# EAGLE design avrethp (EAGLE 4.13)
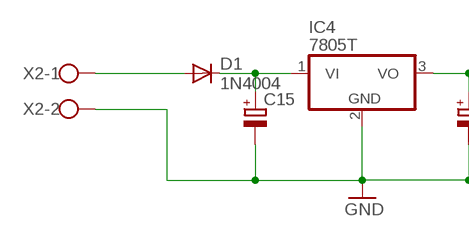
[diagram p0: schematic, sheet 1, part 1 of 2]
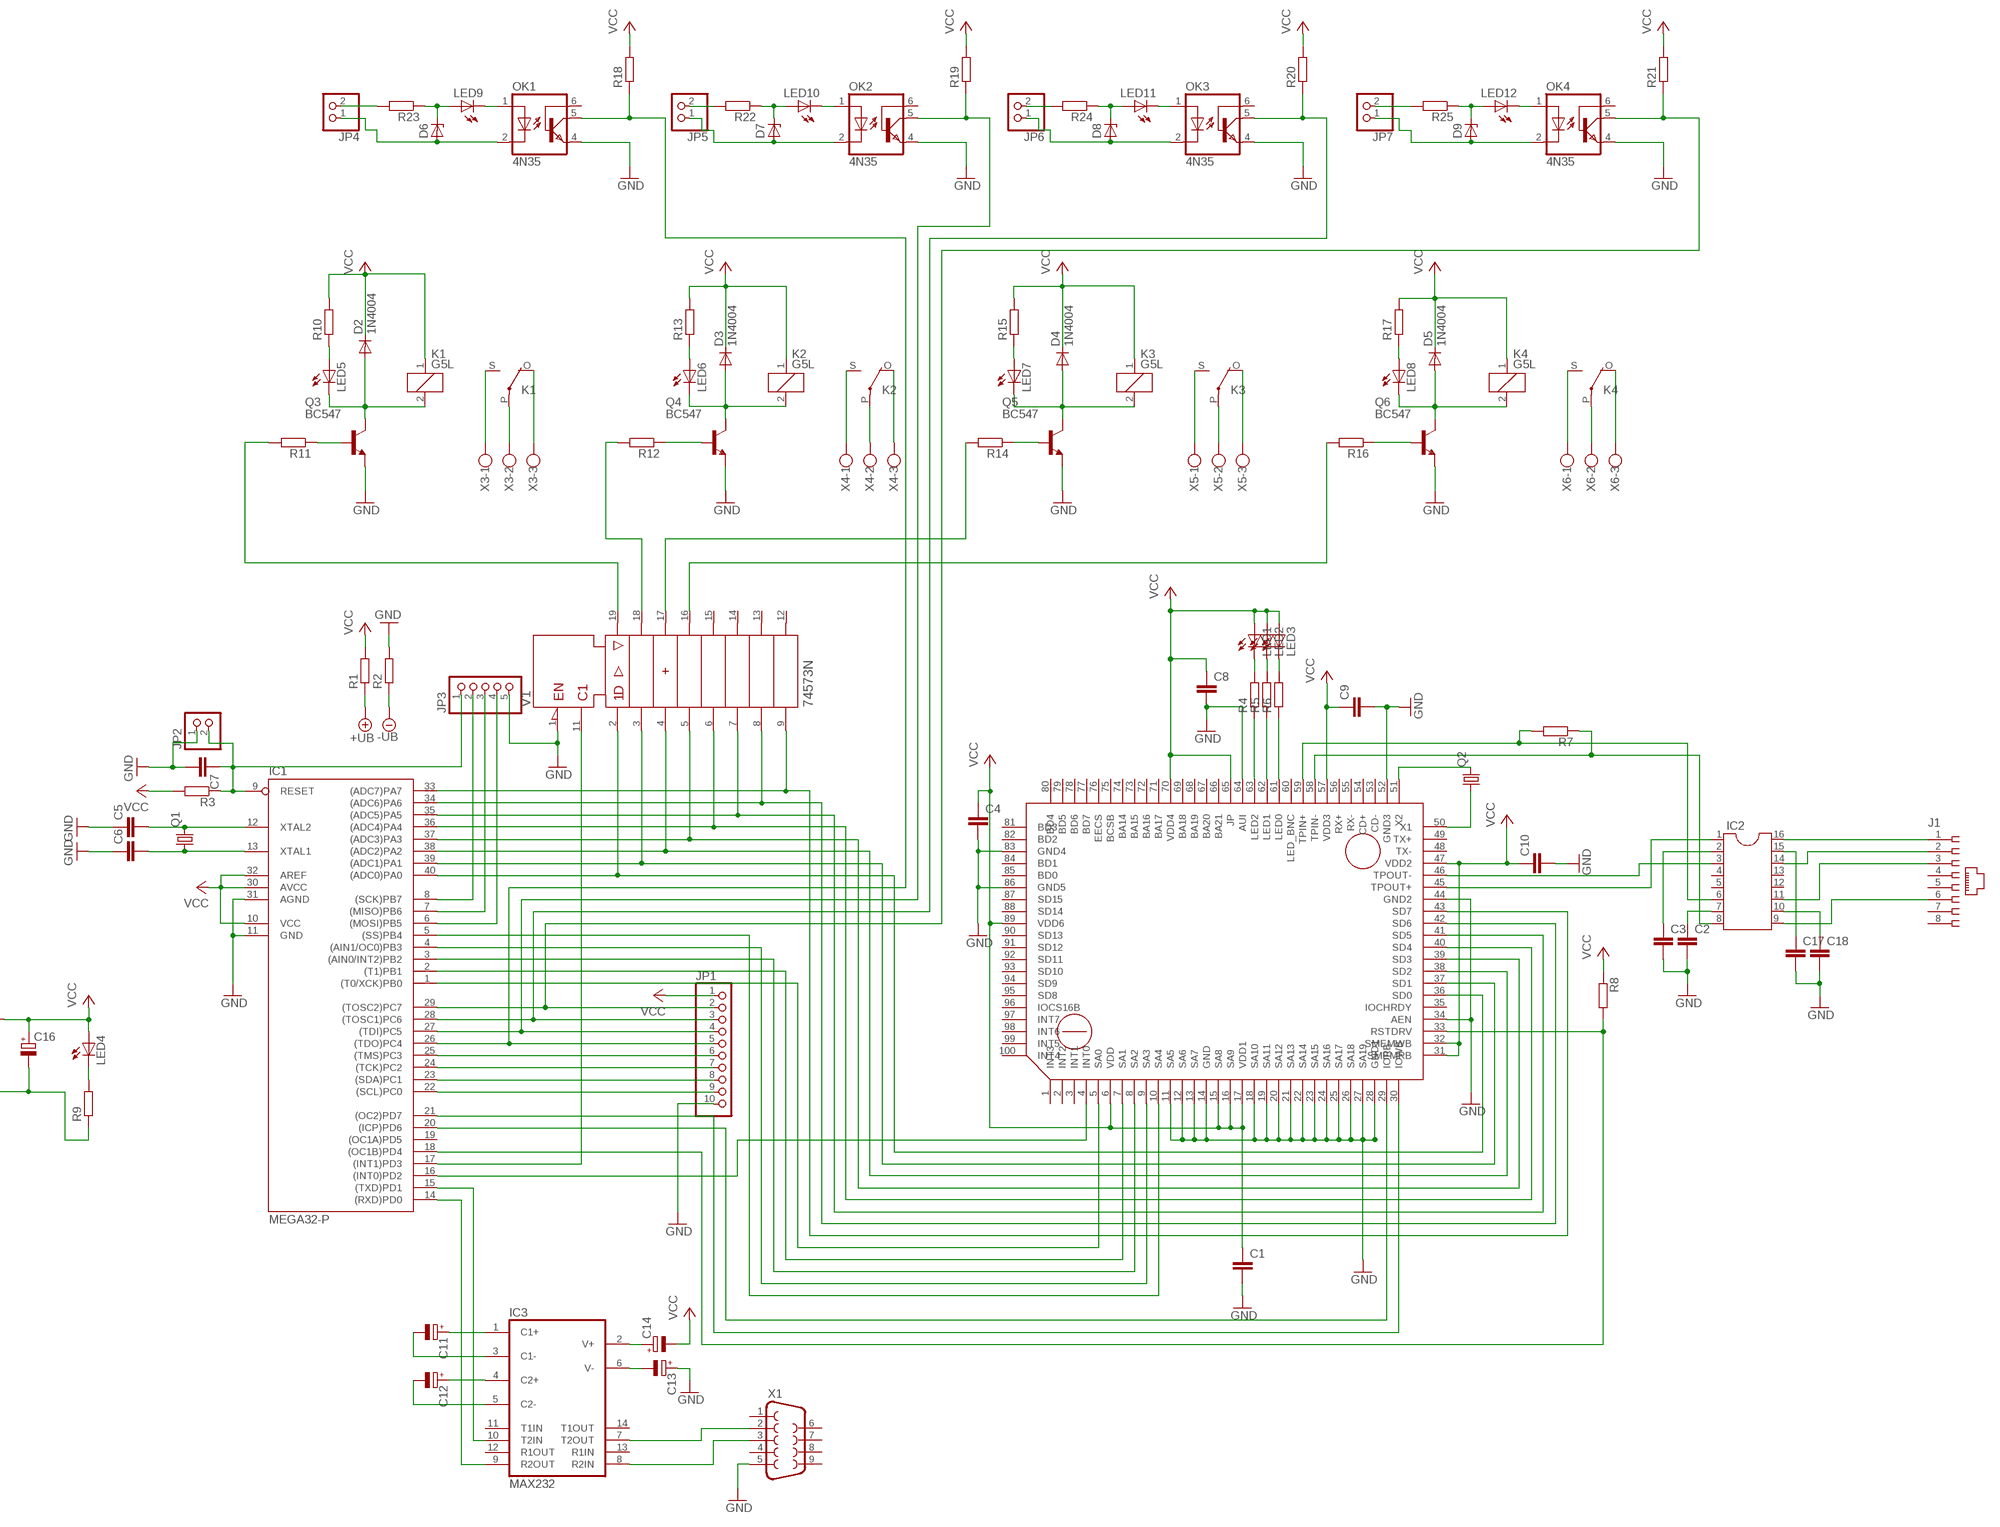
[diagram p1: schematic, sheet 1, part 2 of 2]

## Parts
C1  C-EU050-024X044  [C050-024X044]
C2  C-EU050-024X044  [C050-024X044]
C3  C-EU050-024X044  [C050-024X044]
C4  C-EU050-024X044  [C050-024X044]
C5  C-EU050-024X044  [C050-024X044]
C6  C-EU050-024X044  [C050-024X044]
C7  C-EU050-024X044  [C050-024X044]
C8  C-EU050-024X044  [C050-024X044]
C9  C-EU050-024X044  [C050-024X044]
C10  C-EU050-024X044  [C050-024X044]
C11  CPOL-EUE5-5  [E5-5]
C12  CPOL-EUE5-5  [E5-5]
C13  CPOL-EUE5-5  [E5-5]
C14  CPOL-EUE5-5  [E5-5]
C15  CPOL-EUE5-8.5  [E5-8,5]
C16  CPOL-EUE5-5  [E5-5]
C17  C-EU050-024X044  [C050-024X044]
C18  C-EU050-024X044  [C050-024X044]
D1  1N4004  [DO41-10]
D2  1N4004  [DO41-10]
D3  1N4004  [DO41-10]
D4  1N4004  [DO41-10]
D5  1N4004  [DO41-10]
D6  ZENER-DIODEZD-7.5  [ZDIO-7.5]
D7  ZENER-DIODEZD-7.5  [ZDIO-7.5]
D8  ZENER-DIODEZD-7.5  [ZDIO-7.5]
D9  ZENER-DIODEZD-7.5  [ZDIO-7.5]
IC1  MEGA32-P  [DIL40]
IC2  DIL16  [DIL16]
IC3  MAX232  [DIL16]
IC4  7805T  [TO220H]
J1  520251-4  [520251-4]
JP1  PINHD-1X10  [1X10]
JP2  PINHD-1X2  [1X02]
JP3  PINHD-1X5  [1X05]
JP4  PINHD-1X2  [1X02]
JP5  PINHD-1X2  [1X02]
JP6  PINHD-1X2  [1X02]
JP7  PINHD-1X2  [1X02]
K1  G5L  [G5LE]
K2  G5L  [G5LE]
K3  G5L  [G5LE]
K4  G5L  [G5LE]
LED1  LED3MM  [LED3MM]
LED2  LED3MM  [LED3MM]
LED3  LED3MM  [LED3MM]
LED4  LED3MM  [LED3MM]
LED5  LED3MM  [LED3MM]
LED6  LED3MM  [LED3MM]
LED7  LED3MM  [LED3MM]
LED8  LED3MM  [LED3MM]
LED9  LED3MM  [LED3MM]
LED10  LED3MM  [LED3MM]
LED11  LED3MM  [LED3MM]
LED12  LED3MM  [LED3MM]
OK1  4N35  [DIL06]
OK2  4N35  [DIL06]
OK3  4N35  [DIL06]
OK4  4N35  [DIL06]
Q1  CRYTALHC49U-V  [HC49U-V]
Q2  CRYTALHC49U-V  [HC49U-V]
Q3  BC547  [TO92]
Q4  BC547  [TO92]
Q5  BC547  [TO92]
Q6  BC547  [TO92]
R1  R-EU_0204/7  [0204/7]
R2  R-EU_0204/7  [0204/7]
R3  R-EU_0204/7  [0204/7]
R4  R-EU_0204/7  [0204/7]
R5  R-EU_0204/7  [0204/7]
R6  R-EU_0204/7  [0204/7]
R7  R-EU_0204/7  [0204/7]
R8  R-EU_0204/7  [0204/7]
R9  R-EU_0204/7  [0204/7]
R10  R-EU_0204/7  [0204/7]
R11  R-EU_0204/7  [0204/7]
R12  R-EU_0204/7  [0204/7]
R13  R-EU_0204/7  [0204/7]
R14  R-EU_0204/7  [0204/7]
R15  R-EU_0204/7  [0204/7]
R16  R-EU_0204/7  [0204/7]
R17  R-EU_0204/7  [0204/7]
R18  R-EU_0204/7  [0204/7]
R19  R-EU_0204/7  [0204/7]
R20  R-EU_0204/7  [0204/7]
R21  R-EU_0204/7  [0204/7]
R22  R-EU_0204/7  [0204/7]
R23  R-EU_0204/7  [0204/7]
R24  R-EU_0204/7  [0204/7]
R25  R-EU_0204/7  [0204/7]
U$1  RTL8029RTL8019AS  [RTL8029]
V1  74573N  [DIL20]
X1  F09H  [F09H]
X2  W237-102  [W237-102]
X3  W237-103  [W237-103]
X4  W237-103  [W237-103]
X5  W237-103  [W237-103]
X6  W237-103  [W237-103]

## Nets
+UB: R1.1
-UB: R2.1
GND: C1.2 C2.2 C3.2 C4.2 C5.1 C6.1 C7.2 C8.2 C9.2 C10.2 C13.+ C15.- C16.- C17.2 C18.2 IC1.11(GND) IC1.31(AGND) IC4.2(GND) JP1.10 JP2.1 JP3.5 OK1.4(EMI) OK2.4(EMI) OK3.4(EMI) OK4.4(EMI) Q3.1(E) Q4.1(E) Q5.1(E) Q6.1(E) R2.2 R9.1 U$1.11(SA5) U$1.12(SA6) U$1.13(SA7) U$1.14(GND) U$1.18(SA10) U$1.19(SA11) U$1.20(SA12) U$1.21(SA13) U$1.22(SA14) U$1.23(SA15) U$1.24(SA16) U$1.25(SA17) U$1.26(SA18) U$1.27(SA19) U$1.28(GND1) U$1.34(AEN) U$1.44(GND2) U$1.52(GND3) U$1.64(AUI) U$1.83(GND4) U$1.86(GND5) V1.1(OC\) X1.5 X2.2
N$1: IC2.1 U$1.45(TPOUT+)
N$2: IC1.40((ADC0)PA0) U$1.36(SD0) V1.2(1D)
N$3: IC1.39((ADC1)PA1) U$1.37(SD1) V1.3(2D)
N$4: IC1.38((ADC2)PA2) U$1.38(SD2) V1.4(3D)
N$5: IC1.37((ADC3)PA3) U$1.39(SD3) V1.5(4D)
N$6: IC1.36((ADC4)PA4) U$1.40(SD4) V1.6(5D)
N$7: IC1.35((ADC5)PA5) U$1.41(SD5) V1.7(6D)
N$8: IC1.34((ADC6)PA6) U$1.42(SD6) V1.8(7D)
N$9: IC1.33((ADC7)PA7) U$1.43(SD7) V1.9(8D)
N$10: IC1.1((T0/XCK)PB0) U$1.5(SA0)
N$11: IC1.2((T1)PB1) U$1.7(SA1)
N$12: IC1.3((AIN0/INT2)PB2) U$1.8(SA2)
N$13: IC1.4((AIN1/OC0)PB3) U$1.9(SA3)
N$14: IC1.5((SS)PB4) U$1.10(SA4)
N$15: IC1.16((INT0)PD2) U$1.4(INT0)
N$16: IC1.20((ICP)PD6) U$1.29(IORB)
N$17: IC1.21((OC2)PD7) U$1.30(IOWB)
N$18: Q2.2 U$1.51(X2)
N$19: IC2.3 U$1.46(TPOUT-)
N$20: IC2.8 R7.1 U$1.58(TPIN-)
N$21: IC2.6 R7.2 U$1.59(TPIN+)
N$22: C3.1 IC2.2
N$23: C2.1 IC2.7
N$24: IC1.17((INT1)PD3) V1.11(C)
N$25: IC2.16 J1.1
N$26: IC2.14 J1.2
N$27: IC2.11 J1.3
N$28: IC2.9 J1.6
N$29: JP4.2 R23.2
N$30: IC1.28((TOSC1)PC6) JP1.3 OK3.5(COL) R20.1
N$31: D6.C LED9.A R23.1
N$32: IC1.26((TDO)PC4) JP1.5 OK1.5(COL) R18.1
N$33: IC1.25((TMS)PC3) JP1.6
N$34: IC1.24((TCK)PC2) JP1.7
N$35: IC1.23((SDA)PC1) JP1.8
N$36: IC1.22((SCL)PC0) JP1.9
N$37: Q2.1 U$1.50(X1)
N$38: C5.2 IC1.12(XTAL2) Q1.2
N$39: C6.2 IC1.13(XTAL1) Q1.1
N$40: C7.1 IC1.9(RESET) JP2.2 JP3.1 R3.1
N$41: IC1.8((SCK)PB7) JP3.2
N$42: IC1.7((MISO)PB6) JP3.3
N$43: IC1.6((MOSI)PB5) JP3.4
N$44: IC1.18((OC1B)PD4) R8.2 U$1.33(RSTDRV)
N$45: IC1.15((TXD)PD1) IC3.10(T2IN)
N$46: C11.+ IC3.1(C1+)
N$47: C11.- IC3.3(C1-)
N$48: R4.1 U$1.63(LED2)
N$49: R5.1 U$1.62(LED1)
N$50: R6.1 U$1.61(LED0)
N$51: LED1.K(C) R4.2
N$52: LED2.K(C) R5.2
N$53: LED3.K(C) R6.2
N$54: C12.+ IC3.4(C2+)
N$55: C12.- IC3.5(C2-)
N$56: C14.+ IC3.2(V+)
N$57: C13.- IC3.6(V-)
N$58: IC1.14((RXD)PD0) IC3.9(R2OUT)
N$59: IC3.7(T2OUT) X1.2
N$60: IC3.8(R2IN) X1.3
N$61: D1.A X2.1
N$62: C15.+ D1.C IC4.1(VI)
N$63: LED4.K(C) R9.2
N$64: K1.P(2:P) X3.2
N$65: K1.S(2:S) X3.1
N$66: K1.O(2:O) X3.3
N$67: LED5.A R10.1
N$68: Q3.2(B) R11.1
N$69: D2.A K1.2 LED5.K(C) Q3.3(C)
N$70: R11.2 V1.19(1Q)
N$71: D4.A K3.2 LED7.K(C) Q5.3(C)
N$72: D3.A K2.2 LED6.K(C) Q4.3(C)
N$73: LED6.A R13.1
N$74: LED7.A R15.1
N$75: Q4.2(B) R12.1
N$76: R12.2 V1.18(2Q)
N$77: K2.P(2:P) X4.2
N$78: K2.S(2:S) X4.1
N$79: K2.O(2:O) X4.3
N$80: C17.1 IC2.15
N$81: C18.1 IC2.10
N$82: LED8.A R17.1
N$83: Q5.2(B) R14.1
N$84: IC1.27((TDI)PC5) JP1.4 OK2.5(COL) R19.1
N$85: R14.2 V1.17(3Q)
N$86: K3.P(2:P) X5.2
N$87: K3.S(2:S) X5.1
N$88: K3.O(2:O) X5.3
N$89: LED9.K(C) OK1.1(A)
N$90: D5.A K4.2 LED8.K(C) Q6.3(C)
N$91: IC1.29((TOSC2)PC7) JP1.2 OK4.5(COL) R21.1
N$92: Q6.2(B) R16.1
N$93: R16.2 V1.16(4Q)
N$94: K4.S(2:S) X6.1
N$95: K4.P(2:P) X6.2
N$96: K4.O(2:O) X6.3
N$97: D6.A JP4.1 OK1.2(C)
N$98: JP5.2 R22.2
N$99: D7.C LED10.A R22.1
N$100: D7.A JP5.1 OK2.2(C)
N$101: LED10.K(C) OK2.1(A)
N$102: JP6.2 R24.2
N$103: D8.C LED11.A R24.1
N$104: LED11.K(C) OK3.1(A)
N$105: D8.A JP6.1 OK3.2(C)
N$106: JP7.2 R25.2
N$107: D9.A JP7.1 OK4.2(C)
N$108: LED12.K(C) OK4.1(A)
N$109: D9.C LED12.A R25.1
VCC: C1.1 C4.1 C8.1 C9.1 C10.1 C14.- C16.+ D2.C D3.C D4.C D5.C IC1.10(VCC) IC1.30(AVCC) IC1.32(AREF) IC4.3(VO) JP1.1 K1.1 K2.1 K3.1 K4.1 LED1.A LED2.A LED3.A LED4.A R1.2 R3.2 R8.1 R10.2 R13.2 R15.2 R17.2 R18.2 R19.2 R20.2 R21.2 U$1.6(VDD) U$1.15(SA8) U$1.16(SA9) U$1.17(VDD1) U$1.31(SMEMRB) U$1.32(SMEMWB) U$1.47(VDD2) U$1.57(VDD3) U$1.65(JP) U$1.70(VDD4) U$1.89(VDD6)
Unconnected: IC1.19((OC1A)PD5) IC2.4 IC2.5 IC2.12 IC2.13 IC3.11(T1IN) IC3.12(R1OUT) IC3.13(R1IN) IC3.14(T1OUT) J1.4 J1.5 J1.7 J1.8 OK1.6(BAS) OK2.6(BAS) OK3.6(BAS) OK4.6(BAS) U$1.1(INT3) U$1.2(INT2) U$1.3(INT1) U$1.35(IOCHRDY) U$1.48(TX-) U$1.49(TX+) U$1.53(CD-) U$1.54(CD+) U$1.55(RX-) U$1.56(RX+) U$1.60(LED_BNC) U$1.66(BA21) U$1.67(BA20) U$1.68(BA19) U$1.69(BA18) U$1.71(BA17) U$1.72(BA16) U$1.73(BA15) U$1.74(BA14) U$1.75(BCSB) U$1.76(EECS) U$1.77(BD7) U$1.78(BD6) U$1.79(BD5) U$1.80(BD4) U$1.81(BD3) U$1.82(BD2) U$1.84(BD1) U$1.85(BD0) U$1.87(SD15) U$1.88(SD14) U$1.90(SD13) U$1.91(SD12) U$1.92(SD11) U$1.93(SD10) U$1.94(SD9) U$1.95(SD8) U$1.96(IOCS16B) U$1.97(INT7) U$1.98(INT6) U$1.99(INT5) U$1.100(INT4) V1.12(8Q) V1.13(7Q) V1.14(6Q) V1.15(5Q) X1.1 X1.4 X1.6 X1.7 X1.8 X1.9

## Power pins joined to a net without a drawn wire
+UB: V1.20(+UB)
-UB: V1.10(-UB)
GND: IC3.15(GND)
VCC: IC3.16(VCC)

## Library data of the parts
C1-C10 C17 C18 = rcl:C-EU: CAPACITOR, European symbol
C11-C16 = rcl:CPOL-EU: POLARIZED CAPACITOR, European symbol
D1-D5 = diode:1N4004: DIODE
D6-D9 = diode:ZENER-DIODE: Z-Diode
IC1 = avr:MEGA32-P: MICROCONTROLLER 32 Kbytes FLASH 2 Kbytes SRAM 1 Kbytes EEPROM USART 8-channel 10 bit ADC
IC2 = ic-package:DIL16: Dual In Line
IC3 = maxim:MAX232: RS232 TRANSEIVER
IC4 = linear:78*: Positive VOLTAGE REGULATOR
J1 = con-amp:520251-4: AMP connector
JP1 = pinhead:PINHD-1X10: PIN HEADER
JP2 JP4-JP7 = pinhead:PINHD-1X2: PIN HEADER
JP3 = pinhead:PINHD-1X5: PIN HEADER
K1-K4 = relay:G5L: RELAY 1 x switch, 10 A/120 V AC, 8 A/30 V ADC, Omron
LED1-LED12 = led:LED: LED
OK1-OK4 = optocoupler:4N35: MOTOROLA OPTO COUPLER
Q1 Q2 = crystal:CRYTAL: CRYSTAL
Q3-Q6 = transistor-npn:BC547*: NPN Transistor
R1-R25 = rcl:R-EU_: RESISTOR, European symbol
U$1 = RTL8029:RTL8029
V1 = 74ttl-din:74*573: 8-bit D latch BUS DRIVER
X1 = con-subd:F09: SUB-D
X2 = con-wago-500:W237-102: WAGO SCREW CLAMP
X3-X6 = con-wago-500:W237-103: WAGO SCREW CLAMP

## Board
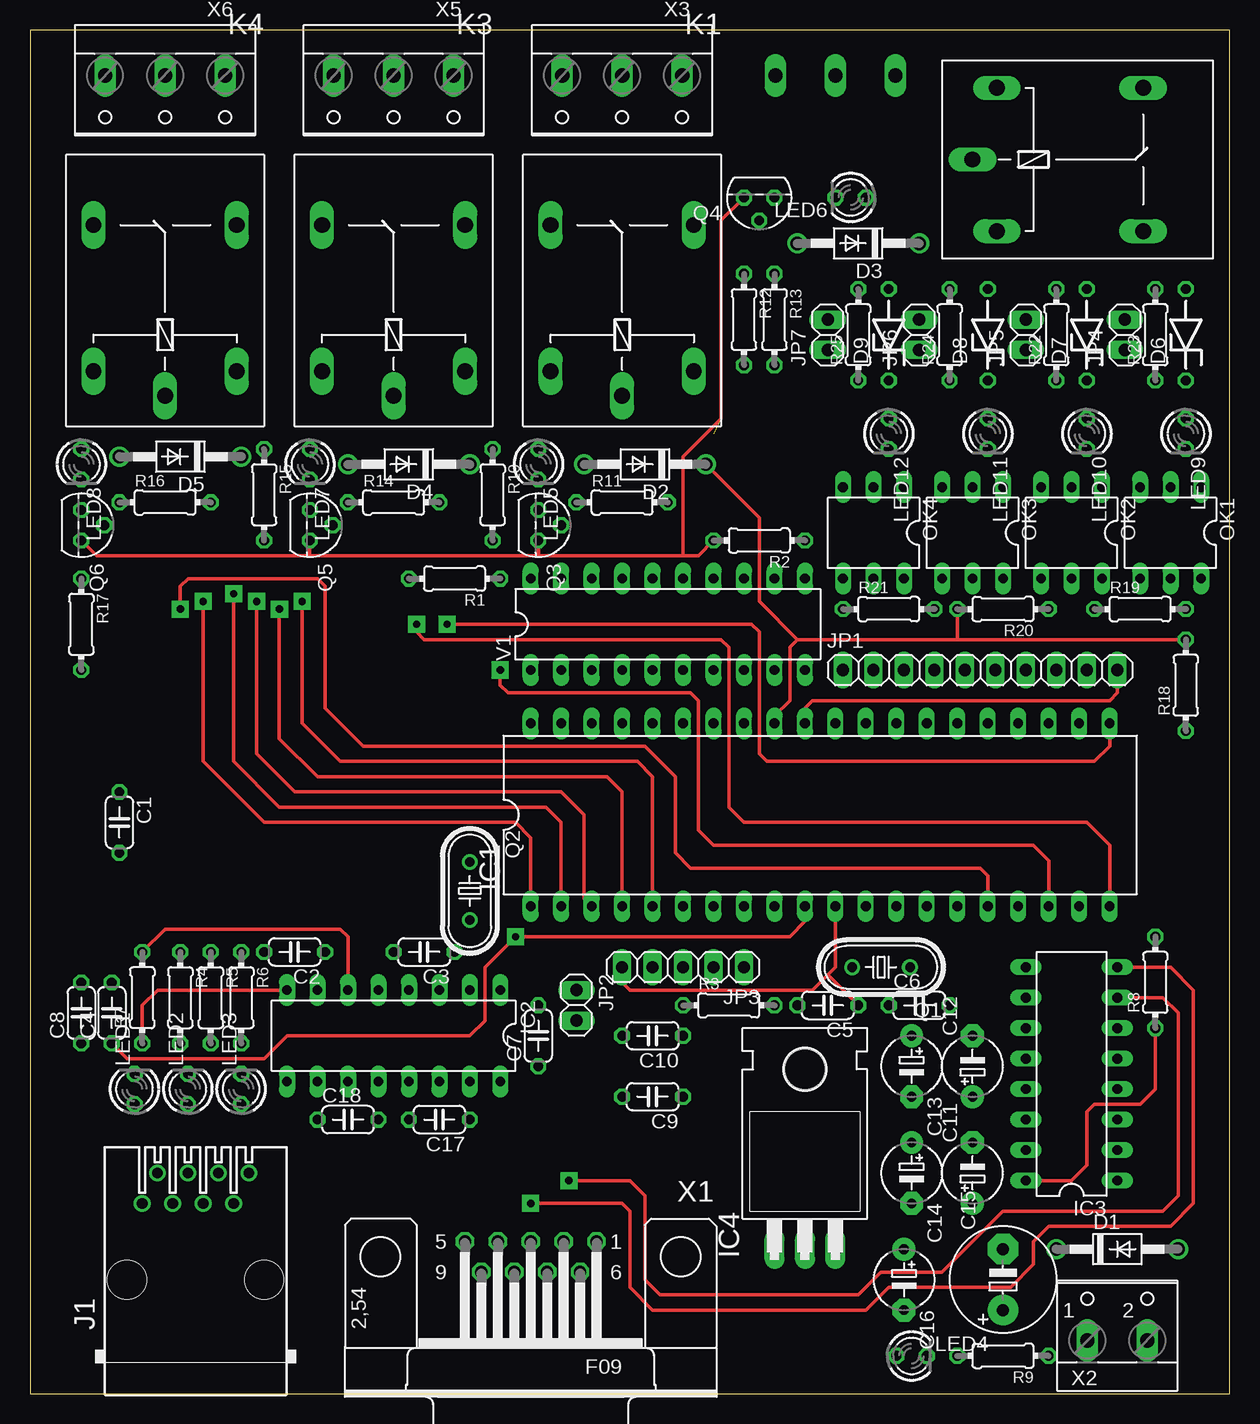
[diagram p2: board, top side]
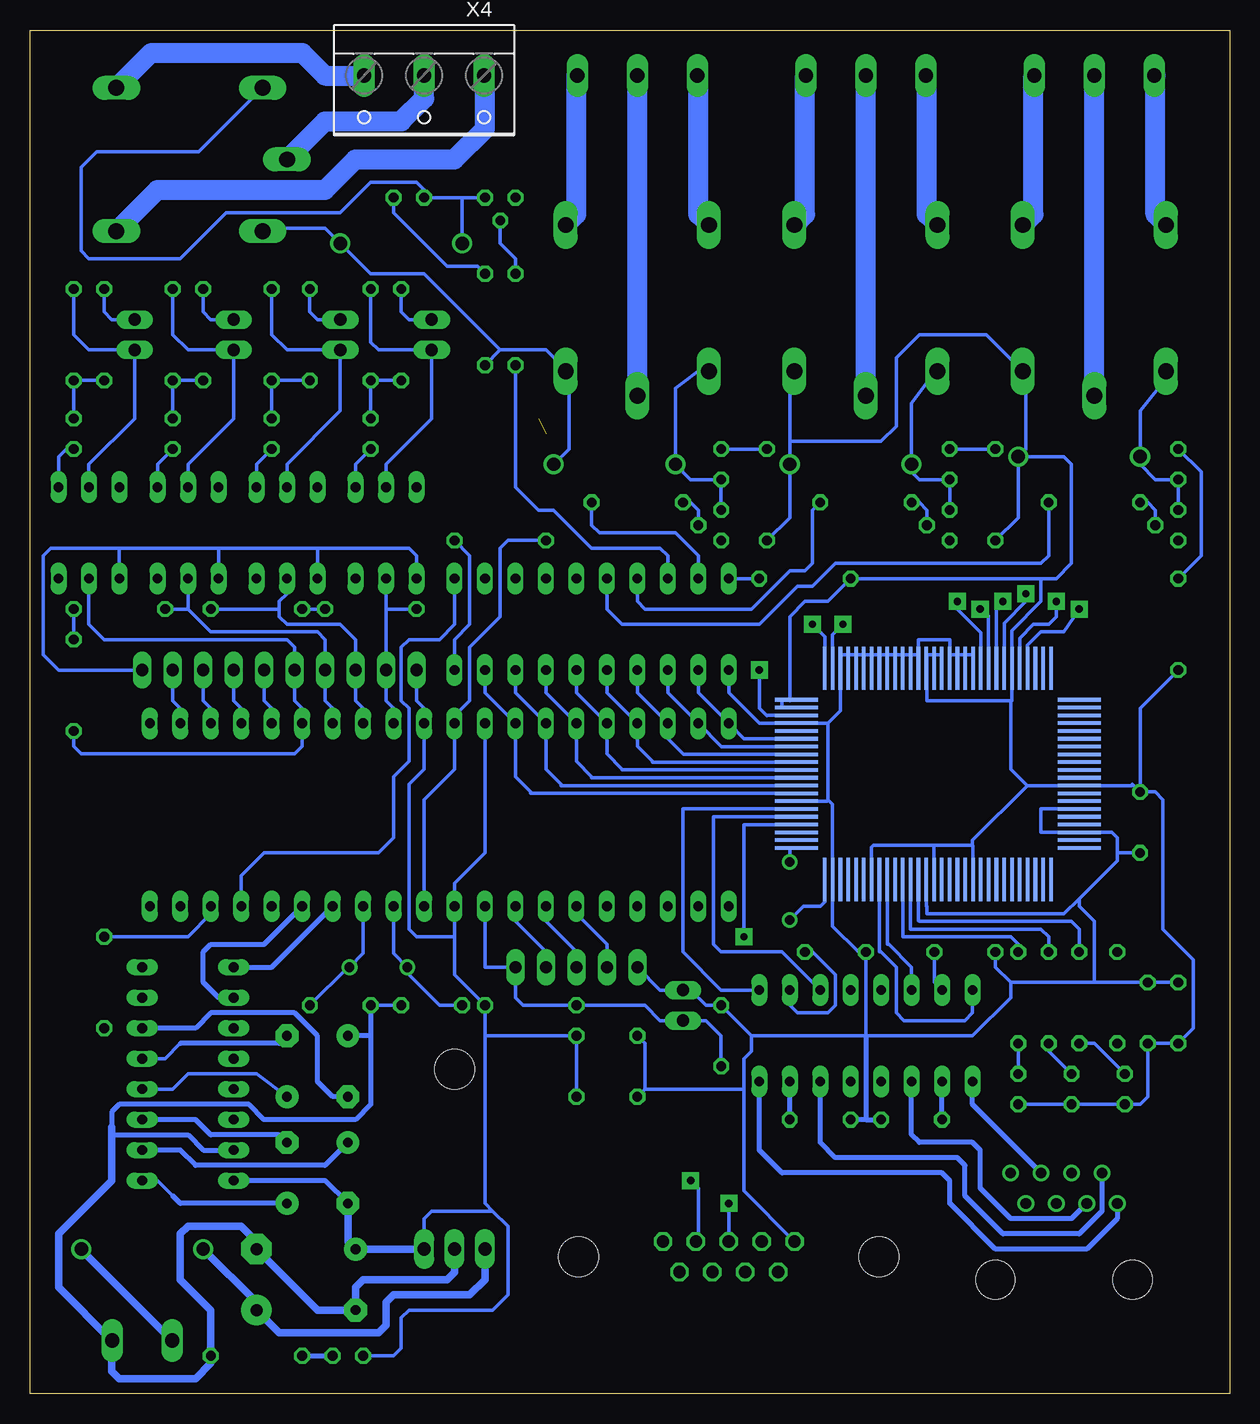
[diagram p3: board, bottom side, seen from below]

Size 100 x 113.66 mm. Coordinates in mm from the lower left corner, seen from the top.
Outline: 0,0 100,0 100,113.66 0,113.66 0,0
Copper layers (1*16): Top 0.035mm / dielectric 1.5mm / Bottom 0.035mm
Design rules "default": minimum track width 10mil, minimum drill 24mil, track to track 8mil, track to pad 8mil, pad to pad 8mil, via to via 8mil, smd to smd 8mil, copper to edge 40mil, drill to drill 8mil, minimum pad ring 10mil, minimum via ring 8mil, stop-mask expansion 4mil, vias tented up to drill 0mil, thermal gap 10mil

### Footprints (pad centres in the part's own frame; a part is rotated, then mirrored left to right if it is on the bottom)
C050-024X044 = drill 0.813 octagon: 1 -2.54,0; 2 2.54,0
E5-5 = drill 0.813 pad 1.905 round: + -2.54,0 | drill 0.813 pad 1.905 octagon: - 2.54,0
E5-8,5 = drill 1.016 pad 2.54 round: + -2.54,0 | drill 1.016 pad 2.54 octagon: - 2.54,0
DO41-10 = drill 1.118 round: A 5.08,0; C -5.08,0
ZDIO-7.5 = drill 0.813 octagon: A 3.81,0; C -3.81,0
DIL40 = drill 0.813 long: 1 -24.13,-7.62; 2 -21.59,-7.62; 3 -19.05,-7.62; 4 -16.51,-7.62; 5 -13.97,-7.62; 6 -11.43,-7.62; 7 -8.89,-7.62; 8 -6.35,-7.62; 9 -3.81,-7.62; 10 -1.27,-7.62; 11 1.27,-7.62; 12 3.81,-7.62; 13 6.35,-7.62; 14 8.89,-7.62; 15 11.43,-7.62; 16 13.97,-7.62; 17 16.51,-7.62; 18 19.05,-7.62; 19 21.59,-7.62; 20 24.13,-7.62; 21 24.13,7.62; 22 21.59,7.62; 23 19.05,7.62; 24 16.51,7.62; 25 13.97,7.62; 26 11.43,7.62; 27 8.89,7.62; 28 6.35,7.62; 29 3.81,7.62; 30 1.27,7.62; 31 -1.27,7.62; 32 -3.81,7.62; 33 -6.35,7.62; 34 -8.89,7.62; 35 -11.43,7.62; 36 -13.97,7.62; 37 -16.51,7.62; 38 -19.05,7.62; 39 -21.59,7.62; 40 -24.13,7.62
DIL16 = drill 0.813 long: 1 -8.89,-3.81; 2 -6.35,-3.81; 3 -3.81,-3.81; 4 -1.27,-3.81; 5 1.27,-3.81; 6 3.81,-3.81; 7 6.35,-3.81; 8 8.89,-3.81; 9 8.89,3.81; 10 6.35,3.81; 11 3.81,3.81; 12 1.27,3.81; 13 -1.27,3.81; 14 -3.81,3.81; 15 -6.35,3.81; 16 -8.89,3.81
TO220H = drill 1.118 long: 1 -2.54,-10.16; 2 0,-10.16; 3 2.54,-10.16 | hole 3.302: 0,4.826
520251-4 = drill 0.889 round: 1 -4.445,6.35; 2 -3.175,8.89; 3 -1.905,6.35; 4 -0.635,8.89; 5 0.635,6.35; 6 1.905,8.89; 7 3.175,6.35; 8 4.445,8.89 | hole 3.251: -5.715,0; 5.715,0
1X10 = drill 1.016 long: 1 -11.43,0; 2 -8.89,0; 3 -6.35,0; 4 -3.81,0; 5 -1.27,0; 6 1.27,0; 7 3.81,0; 8 6.35,0; 9 8.89,0; 10 11.43,0
1X02 = drill 1.016 long: 1 -1.27,0; 2 1.27,0
1X05 = drill 1.016 long: 1 -5.08,0; 2 -2.54,0; 3 0,0; 4 2.54,0; 5 5.08,0
G5LE = drill 1.321 long: 1 -7.493,-5.969; 2 -7.493,5.969; O 4.699,5.969; P -9.525,0; S 4.699,-5.969
LED3MM = drill 0.813 octagon: A -1.27,0; K 1.27,0
DIL06 = drill 0.813 long: 1 -2.54,-3.81; 2 0,-3.81; 3 2.54,-3.81; 4 2.54,3.81; 5 0,3.81; 6 -2.54,3.81
HC49U-V = drill 0.813 round: 1 -2.413,0; 2 2.413,0
TO92 = drill 0.813 octagon: 1 1.27,0; 2 0,1.905; 3 -1.27,0
0204/7 = drill 0.813 octagon: 1 -3.81,0; 2 3.81,0
RTL8029 = smd 2.4 x 0.3: 1 -7.799,10.347; 2 -7.799,9.697; 3 -7.799,9.047; 4 -7.799,8.397; 5 -7.799,7.747; 6 -7.799,7.097; 7 -7.799,6.447; 8 -7.799,5.797; 9 -7.799,5.147; 10 -7.799,4.497; 11 -7.799,3.847; 12 -7.799,3.197; 13 -7.799,2.547; 14 -7.799,1.897; 15 -7.799,1.247; 16 -7.799,0.597; 17 -7.799,-0.053; 18 -7.799,-0.703; 19 -7.799,-1.353; 20 -7.799,-2.003; 21 -7.799,-2.653; 22 -7.799,-3.303; 23 -7.799,-3.953; 24 -7.799,-4.603; 25 -7.799,-5.253; 26 -7.799,-5.903; 27 -7.799,-6.553; 28 -7.799,-7.203; 29 -7.799,-7.853; 30 -7.799,-8.503; 51 8.601,-8.503; 52 8.601,-7.853; 53 8.601,-7.203; 54 8.601,-6.553; 55 8.601,-5.903; 56 8.601,-5.253; 57 8.601,-4.603; 58 8.601,-3.953; 59 8.601,-3.303; 60 8.601,-2.653; 61 8.601,-2.003; 62 8.601,-1.353; 63 8.601,-0.703; 64 8.601,-0.053; 65 8.601,0.597; 66 8.601,1.247; 67 8.601,1.897; 68 8.601,2.547; 69 8.601,3.197; 70 8.601,3.847; 71 8.601,4.497; 72 8.601,5.147; 73 8.601,5.797; 74 8.601,6.447; 75 8.601,7.097; 76 8.601,7.747; 77 8.601,8.397; 78 8.601,9.047; 79 8.601,9.697; 80 8.601,10.347; 101 -8.999,10.347; 102 -8.999,9.697; 103 -8.999,9.047; 104 -8.999,8.397; 105 -8.999,7.747; 106 -8.999,7.097; 107 -8.999,6.447; 108 -8.999,5.797; 109 -8.999,5.147; 110 -8.999,4.497; 111 -8.999,3.847; 112 -8.999,3.197; 113 -8.999,2.547; 114 -8.999,1.897; 115 -8.999,1.247; 116 -8.999,0.597; 117 -8.999,-0.053; 118 -8.999,-0.703; 119 -8.999,-1.353; 120 -8.999,-2.003; 121 -8.999,-2.653; 122 -8.999,-3.303; 123 -8.999,-3.953; 124 -8.999,-4.603; 125 -8.999,-5.253; 126 -8.999,-5.903; 127 -8.999,-6.553; 128 -8.999,-7.203; 129 -8.999,-7.853; 130 -8.999,-8.503; 151 9.801,-8.503; 152 9.801,-7.853; 153 9.801,-7.203; 154 9.801,-6.553; 155 9.801,-5.903; 156 9.801,-5.253; 157 9.801,-4.603; 158 9.801,-3.953; 159 9.801,-3.303; 160 9.801,-2.653; 161 9.801,-2.003; 162 9.801,-1.353; 163 9.801,-0.703; 164 9.801,-0.053; 165 9.801,0.597; 166 9.801,1.247; 167 9.801,1.897; 168 9.801,2.547; 169 9.801,3.197; 170 9.801,3.847; 171 9.801,4.497; 172 9.801,5.147; 173 9.801,5.797; 174 9.801,6.447; 175 9.801,7.097; 176 9.801,7.747; 177 9.801,8.397; 178 9.801,9.047; 179 9.801,9.697; 180 9.801,10.347 | smd 0.3 x 2.4: 31 -5.774,-10.278; 32 -5.124,-10.278; 33 -4.474,-10.278; 34 -3.824,-10.278; 35 -3.174,-10.278; 36 -2.524,-10.278; 37 -1.874,-10.278; 38 -1.224,-10.278; 39 -0.574,-10.278; 40 0.076,-10.278; 41 0.726,-10.278; 42 1.376,-10.278; 43 2.026,-10.278; 44 2.676,-10.278; 45 3.326,-10.278; 46 3.976,-10.278; 47 4.626,-10.278; 48 5.276,-10.278; 49 5.926,-10.278; 50 6.576,-10.278; 81 6.576,12.122; 82 5.926,12.122; 83 5.276,12.122; 84 4.626,12.122; 85 3.976,12.122; 86 3.326,12.122; 87 2.676,12.122; 88 2.026,12.122; 89 1.376,12.122; 90 0.726,12.122; 91 0.076,12.122; 92 -0.574,12.122; 93 -1.224,12.122; 94 -1.874,12.122; 95 -2.524,12.122; 96 -3.174,12.122; 97 -3.824,12.122; 98 -4.474,12.122; 99 -5.124,12.122; 100 -5.774,12.122; 131 -5.774,-11.478; 132 -5.124,-11.478; 133 -4.474,-11.478; 134 -3.824,-11.478; 135 -3.174,-11.478; 136 -2.524,-11.478; 137 -1.874,-11.478; 138 -1.224,-11.478; 139 -0.574,-11.478; 140 0.076,-11.478; 141 0.726,-11.478; 142 1.376,-11.478; 143 2.026,-11.478; 144 2.676,-11.478; 145 3.326,-11.478; 146 3.976,-11.478; 147 4.626,-11.478; 148 5.276,-11.478; 149 5.926,-11.478; 150 6.576,-11.478; 181 6.576,13.322; 182 5.926,13.322; 183 5.276,13.322; 184 4.626,13.322; 185 3.976,13.322; 186 3.326,13.322; 187 2.676,13.322; 188 2.026,13.322; 189 1.376,13.322; 190 0.726,13.322; 191 0.076,13.322; 192 -0.574,13.322; 193 -1.224,13.322; 194 -1.874,13.322; 195 -2.524,13.322; 196 -3.174,13.322; 197 -3.824,13.322; 198 -4.474,13.322; 199 -5.124,13.322; 200 -5.774,13.322
DIL20 = drill 0.813 long: 1 -11.43,-3.81; 2 -8.89,-3.81; 3 -6.35,-3.81; 4 -3.81,-3.81; 5 -1.27,-3.81; 6 1.27,-3.81; 7 3.81,-3.81; 8 6.35,-3.81; 9 8.89,-3.81; 10 11.43,-3.81; 11 11.43,3.81; 12 8.89,3.81; 13 6.35,3.81; 14 3.81,3.81; 15 1.27,3.81; 16 -1.27,3.81; 17 -3.81,3.81; 18 -6.35,3.81; 19 -8.89,3.81; 20 -11.43,3.81
F09H = drill 1.016 octagon: 1 -5.486,-1.27; 2 -2.743,-1.27; 3 0,-1.27; 4 2.743,-1.27; 5 5.486,-1.27; 6 -4.115,1.27; 7 -1.372,1.27; 8 1.372,1.27; 9 4.115,1.27 | hole 3.302: -12.522,0; 12.522,0
W237-102 = drill 1.194 long: 1 -2.5,-1.27; 2 2.5,-1.27
W237-103 = drill 1.194 long: 1 -5,-1.29; 2 0,-1.29; 3 5,-1.29

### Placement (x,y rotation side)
C1  7.45,47.62 270 top
C2  22.06,36.83 180 top
C3  32.86,36.83 180 top
C4  6.82,31.75 90 top
C5  66.51,32.38 180 top
C6  74.13,32.38 0 top
C7  42.38,29.84 90 top
C8  4.28,31.75 90 top
C9  51.91,24.76 180 top
C10  51.91,29.84 180 top
C11  78.58,18.41 90 top
C12  78.58,27.3 90 top
C13  73.5,27.3 270 top
C14  73.5,18.41 270 top
C15  81.12,9.52 90 top
C16  72.86,9.52 270 top
C17  34.12,22.86 180 top
C18  26.51,22.86 0 top
D1  90.64,12.06 0 top
D2  51.27,77.47 180 top
D3  69.05,95.88 180 top
D4  31.59,77.47 180 top
D5  12.54,78.1 180 top
D6  96.36,88.26 90 top
D7  88.1,88.26 90 top
D8  79.84,88.26 90 top
D9  71.59,88.26 90 top
IC1  65.88,48.26 0 top
IC2  30.31,29.84 180 top
IC3  86.83,26.67 90 top
IC4  64.61,22.22 0 top
J1  13.81,9.52 0 top
JP1  79.21,60.32 0 top
JP2  45.56,32.38 270 top
JP3  54.45,35.55 180 top
JP4  91.28,88.26 90 top
JP5  83.02,88.26 90 top
JP6  74.13,88.26 90 top
JP7  66.51,88.26 90 top
K1  49.37,92.7 90 top
K2  88.1,102.87 0 top
K3  30.31,92.7 90 top
K4  11.27,92.7 90 top
LED1  8.73,25.4 90 top
LED2  13.17,25.4 90 top
LED3  17.62,25.4 90 top
LED4  73.5,3.17 0 top
LED5  42.38,77.47 270 top
LED6  68.42,99.69 180 top
LED7  23.33,77.47 270 top
LED8  4.28,77.47 270 top
LED9  96.36,80 270 top
LED10  88.1,80 270 top
LED11  79.84,80 270 top
LED12  71.59,80 270 top
OK1  95.09,71.75 180 top
OK2  86.83,71.75 180 top
OK3  78.58,71.75 180 top
OK4  70.32,71.75 180 top
Q1  70.96,35.55 180 top
Q2  36.67,41.91 270 top
Q3  42.38,72.39 270 top
Q4  60.8,99.69 180 top
Q5  23.33,72.39 270 top
Q6  4.28,72.39 270 top
R1  35.4,67.94 180 top
R2  60.8,71.12 180 top
R3  58.26,32.38 0 top
R4  12.54,33.02 270 top
R5  15.08,33.02 270 top
R6  17.62,33.02 270 top
R7  9.36,33.02 90 top
R8  93.81,34.29 90 top
R9  81.12,3.17 180 top
R10  38.57,74.92 270 top
R11  49.37,74.29 0 top
R12  59.53,89.53 270 top
R13  62.07,89.53 270 top
R14  30.31,74.29 0 top
R15  19.52,74.92 270 top
R16  11.27,74.29 0 top
R17  4.28,64.13 270 top
R18  96.36,59.05 90 top
R19  92.55,65.4 0 top
R20  81.12,65.4 180 top
R21  71.59,65.4 0 top
R22  85.56,88.26 90 top
R23  93.81,88.26 90 top
R24  76.67,88.26 90 top
R25  69.05,88.26 90 top
U$1  25.23,52.06 270 bottom
V1  53.18,64.13 0 top
X1  41.75,11.43 180 top
X2  90.64,5.71 0 top
X3  49.37,108.58 180 top
X4  67.15,108.58 180 bottom
X5  30.31,108.58 180 top
X6  11.27,108.58 180 top

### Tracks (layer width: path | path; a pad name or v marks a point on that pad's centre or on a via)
+UB
  Bottom 0.305: R1.1 V1.20
-UB
  Bottom 0.305: R2.1 63.34,69.84 63.34,64.13 64.61,62.86 V1.10
GND  (1 unrouted)
  Top 0.305: IC1.11 67.15,35.55 66.51,34.92 | 66.51,34.92 65.24,33.65 50,33.65 49.37,34.29 JP3.5 | 66.51,34.92 C5.1 | JP1.10 90.64,58.42 90.01,57.78 65.24,57.78 64.61,57.15 IC1.31 | Q6.1 5.55,69.84 23.33,69.84 | 54.45,69.84 55.72,69.84 R2.2 | 54.45,69.84 42.38,69.84 | 42.38,69.84 23.33,69.84 | 42.38,69.84 Q3.1 | 23.33,69.84 Q5.1 | Q4.1 57.62,97.78 57.62,83.18 57.62,81.28 54.45,78.1 54.45,69.84
  Bottom 0.305: 31.59,61.59 32.44,61.59 U$1.28 32.44,56.93 33.49,55.88 | 31.59,61.59 30.95,61.59 | 30.95,61.59 30.31,61.59 | 30.31,61.59 29.68,61.59 | 29.68,61.59 29.05,61.59 | 29.05,61.59 28.41,61.59 | 28.41,61.59 27.78,61.59 | 27.78,61.59 27.14,61.59 | 27.14,61.59 26.59,61.59 | U$1.27 31.79,61.59 31.59,61.59 | U$1.26 31.14,61.59 30.95,61.59 | U$1.25 30.49,61.59 30.31,61.59 | U$1.24 29.84,61.59 29.68,61.59 | U$1.23 29.19,61.59 29.05,61.59 | U$1.22 28.54,61.59 28.41,61.59 | U$1.21 27.89,61.59 27.78,61.59 | U$1.20 27.24,61.59 27.14,61.59 | 26.59,61.59 U$1.19 | 26.59,61.59 25.94,61.59 U$1.18 25.94,62.86 23.33,62.86 23.33,61.59 | U$1.14 23.34,59.69 23.33,59.69 23.33,61.59 | U$1.13 22.69,61.59 22.7,61.59 | 23.33,61.59 22.7,61.59 | U$1.12 22.04,61.59 22.06,61.59 | 22.7,61.59 22.06,61.59 | U$1.11 21.39,61.59 22.06,61.59 | U$1.44 33.63,49.39 arc-90 33.49,49.53 | 33.49,49.53 33.49,55.88 | 33.49,55.88 35.4,55.88 arc-180 35.4,55.89 U$1.34 38.56,55.89 38.57,55.88 39.2,55.88 41.75,58.42 V1.1 | 33.49,49.53 33.09,49.12 U$1.52 33.09,38.96 30.95,36.83 C3.2 30.31,29.84 | U$1.86 15.71,48.74 15.71,46.79 U$1.83 9.8,46.79 9.36,46.35 9.36,45.08 | U$1.64 25.29,40.64 25.23,40.64 25.23,40 13.81,40 12.54,41.27 | 12.54,41.27 9.36,44.45 9.36,45.08 | C2.2 19.52,35.55 18.25,34.29 | 12.54,41.27 12.54,40.64 11.27,39.37 11.27,34.29 | 18.25,34.29 18.25,33.02 21.43,29.84 30.31,29.84 | 9.36,45.08 C1.2 | IC1.11 67.15,49.53 64.61,52.06 IC1.31 64.61,56.51 63.34,57.78 63.34,62.23 60.8,64.77 60.8,70.48 60.16,71.12 R2.2 | JP3.5 47.46,33.65 JP2.1 44.92,33.65 43.65,32.38 C7.2 39.84,29.84 | 39.84,29.84 30.31,29.84 | C5.1 C6.1 | X1.5 40.48,16.91 40.48,25.4
  Bottom 0.305: 40.48,25.4 40.48,27.94 39.84,28.57 39.84,29.84 | 18.25,34.29 11.27,34.29 | 11.27,34.29 C4.2 C8.2 | 40.48,25.4 43.02,25.4 | 43.02,25.4 44.92,25.4 | 48.73,25.4 C9.2 | 43.02,25.4 48.73,25.4 | C10.2 48.73,29.21 48.73,25.4 | OK4.4 67.78,69.84 68.42,70.48 76.03,70.48 | 84.29,70.48 76.03,70.48 | 84.29,70.48 OK2.4 | 76.03,70.48 OK3.4 | 95.09,70.48 95.72,70.48 | 95.09,70.48 93.81,70.48 | 93.81,70.48 93.18,70.48 | 93.81,70.48 92.55,70.48 | 92.55,70.48 84.29,70.48 | 92.55,70.48 OK1.4 | JP1.10 97.62,60.32 98.9,61.59 98.9,69.84 98.26,70.48 95.09,70.48
  Bottom 0.406: 93.18,22.22 93.18,23.49 92.55,24.12 81.75,24.12 80.48,22.86 72.86,22.86 71.59,24.12 71.59,29.84 | IC3.15 85.56,20.32 86.83,21.59 93.18,21.59 | C6.1 71.59,29.84 | 71.59,29.84 C13.+ | 30.31,22.86 C17.2 | 30.31,22.86 C18.2 | 30.31,29.84 30.31,22.86
  Bottom 0.61: 93.18,4.4 X2.2 93.18,4.44 | 93.18,4.44 93.18,1.9 92.55,1.27 86.2,1.27 84.93,2.53 R9.1 84.93,6.98 87.47,9.52 87.47,13.33 86.83,13.97 82.39,13.97 81.12,12.7 C15.- 76.03,6.98 C16.- 72.86,8.89 72.22,9.52 65.24,9.52 64.61,10.16 IC4.2 | 93.18,4.44 97.62,8.89 97.62,13.33 93.18,17.78 93.18,21.59 93.18,22.22
N$1
  Bottom 0.305: U$1.45 45.56,48.74 45.56,36.83 42.38,33.65 IC2.1
N$2
  Bottom 0.305: U$1.36 40.46,54.59 IC1.40 44.29,58.42 V1.2
N$3
  Bottom 0.305: U$1.37 42.35,53.94 IC1.39 46.83,58.42 V1.3
N$4
  Bottom 0.305: U$1.38 45.51,53.29 46.83,54.61 IC1.38 49.37,58.42 V1.4
N$5
  Bottom 0.305: U$1.39 48.1,52.64 48.1,52.7 49.37,53.97 IC1.37 51.91,58.42 V1.5
N$6
  Bottom 0.305: U$1.40 50.64,51.99 50.64,52.06 51.91,53.34 IC1.36 54.45,58.42 V1.6
N$7
  Bottom 0.305: U$1.41 53.18,51.34 53.18,51.43 54.45,52.7 IC1.35 56.99,58.42 V1.7
N$8
  Bottom 0.305: U$1.42 55.72,50.69 55.72,50.8 56.99,52.06 IC1.34 59.53,58.42 V1.8
N$9
  Bottom 0.305: U$1.43 58.26,50.04 58.26,50.16 59.53,51.43 IC1.33 62.07,58.42 V1.9
N$10  (via drill 0.6 pad 1.42)
  Top 0.305: v14.44,66.03 14.44,52.7 19.52,47.62 40.48,47.62 41.75,46.35 IC1.1
  Bottom 0.305: U$1.5 17.49,62.99 16.34,64.13 15.08,64.13 14.44,64.77 v14.44,66.03
N$11  (via drill 0.6 pad 1.42)
  Top 0.305: IC1.2 44.29,47.62 43.02,48.89 20.79,48.89 16.98,52.7 v16.98,66.67
  Bottom 0.305: U$1.7 18.79,64.23 16.98,66.03 v16.98,66.67
N$12  (via drill 0.6 pad 1.42)
  Top 0.305: v18.89,66.03 18.89,53.34 22.06,50.16 44.29,50.16 46.19,48.26 46.19,41.27 IC1.3
  Bottom 0.305: U$1.8 19.44,65.48 v18.89,66.03
N$13  (via drill 0.6 pad 1.42)
  Top 0.305: IC1.4 49.37,50.16 48.1,51.43 23.97,51.43 20.79,54.61 v20.79,65.4
  Bottom 0.305: U$1.9 20.09,64.83 v20.79,65.4
N$14  (via drill 0.6 pad 1.42)
  Top 0.305: IC1.5 51.91,51.43 50.64,52.7 25.87,52.7 22.7,55.88 v22.7,66.03
  Bottom 0.305: U$1.10 20.74,63.44 22.7,65.4 v22.7,66.03
N$15  (via drill 0.6 pad 1.42)
  Top 0.305: v12.54,65.4 12.54,67.31 13.17,67.94 23.97,67.94 24.6,67.31 24.6,57.15 27.78,53.97 51.27,53.97 53.81,51.43 53.81,45.08 55.08,43.81 79.21,43.81 79.84,43.18 IC1.16
  Bottom 0.305: U$1.4 16.84,62.37 15.71,63.5 13.81,63.5 v12.54,65.4
N$16  (via drill 0.6 pad 1.42)
  Top 0.305: IC1.20 90.01,45.72 88.1,47.62 59.53,47.62 58.26,48.89 58.26,62.23 57.62,62.86 32.86,62.86 32.22,63.5 v32.22,64.13
  Bottom 0.305: U$1.29 33.09,63.26 v32.22,64.13
N$17  (via drill 0.6 pad 1.42)
  Top 0.305: v34.76,64.13 60.16,64.13 60.8,63.5 60.8,53.34 61.43,52.7 88.73,52.7 90.01,53.97 IC1.21
  Bottom 0.305: U$1.30 33.74,63.11 v34.76,64.13
N$18
  Bottom 0.305: U$1.51 33.74,41.02 34.12,40.64 35.52,40.64 Q2.2
N$19
  Bottom 0.305: U$1.46 43.02,48.09 43.02,37.46 42.38,36.83 37.3,36.83 IC2.3
N$20
  Top 0.305: R7.1 9.36,32.38 10.63,33.65 IC2.8
  Bottom 0.305: U$1.58 29.19,36.83 29.05,36.83 27.78,35.55 27.78,31.75 27.14,31.11 22.06,31.11 21.43,31.75 IC2.8
N$21
  Top 0.305: R7.2 11.27,38.73 25.87,38.73 26.51,38.09 IC2.6
  Bottom 0.305: U$1.59 28.54,37.46 28.41,37.46 26.51,35.55 IC2.6
N$22
  Bottom 0.305: IC2.2 36.67,32.38 36.03,31.75 33.49,31.75 32.86,32.38 32.86,34.92 34.76,36.83 C3.1
N$23
  Bottom 0.305: IC2.7 24.6,34.29 C2.1
N$24
  Bottom 0.305: IC1.17 82.39,43.18 80.48,45.08 70.96,45.08 69.69,46.35 69.69,51.43 68.42,52.7 68.42,57.15 69.05,57.78 69.05,62.23 68.42,62.86 65.88,62.86 64.61,64.13 V1.11
N$25
  Bottom 0.406: J1.1 9.36,14.6 11.9,12.06 19.52,12.06 23.33,15.87 23.33,17.78 23.97,18.41 37.3,18.41 39.2,20.32 IC2.16
N$26
  Bottom 0.406: J1.2 10.63,15.23 12.54,13.33 18.89,13.33 22.06,16.51 22.06,19.05 22.7,19.68 32.86,19.68 34.12,20.95 IC2.14
N$27
  Bottom 0.406: J1.3 13.17,14.6 18.25,14.6 20.79,17.14 20.79,20.32 21.43,20.95 25.87,20.95 26.51,21.59 IC2.11
N$28
  Bottom 0.406: J1.6 21.43,24.12 IC2.9
N$29
  Bottom 0.305: JP4.2 93.18,89.53 93.81,90.17 R23.2
N$30
  Bottom 0.305: IC1.28 72.22,57.15 72.86,57.78 JP1.3 72.86,62.86 74.13,64.13 78.58,64.13 79.21,64.77 79.21,65.4 | 79.21,65.4 79.21,66.03 78.58,66.67 OK3.5 | R20.1 79.21,65.4
N$31
  Bottom 0.305: LED9.A D6.C R23.1
N$32
  Bottom 0.305: OK1.5 95.09,64.13 93.81,62.86 78.58,62.86 77.94,62.23 JP1.5 77.94,57.78 77.31,57.15 IC1.26 77.31,53.97 77.94,53.34 95.72,53.34 96.36,53.97 R18.1
N$33
  Bottom 0.305: IC1.25 79.84,57.15 80.48,57.78 JP1.6
N$34
  Bottom 0.305: IC1.24 82.39,57.15 83.02,57.78 JP1.7
N$35
  Bottom 0.305: IC1.23 84.93,57.15 85.56,57.78 JP1.8
N$36
  Bottom 0.305: IC1.22 87.47,57.15 88.1,57.78 JP1.9
N$37
  Bottom 0.305: U$1.50 36.67,45.49 Q2.1
N$38
  Bottom 0.305: IC1.12 69.69,36.7 Q1.2 68.42,35.55 68.42,34.92 65.88,32.38 C5.2
N$39
  Bottom 0.305: IC1.13 72.22,36.7 Q1.1 73.5,35.55 C6.2
N$40
  Bottom 0.305: IC1.9 62.07,35.55 JP3.1 59.53,33.02 58.89,32.38 R3.1 48.73,32.38 47.46,31.11 JP2.2 43.65,31.11 42.38,29.84 C7.1
N$41
  Bottom 0.305: JP3.2 56.99,36.83 59.53,39.37 IC1.8
N$42
  Bottom 0.305: JP3.3 54.45,36.83 56.99,39.37 IC1.7
N$43
  Bottom 0.305: JP3.4 51.91,37.46 54.45,40 IC1.6
N$44  (via drill 0.6 pad 1.42)
  Top 0.305: v39.2,60.32 39.2,59.05 39.84,58.42 55.08,58.42 55.72,57.78 55.72,46.98 56.99,45.72 83.66,45.72 84.93,44.45 IC1.18
  Bottom 0.305: U$1.33 38.54,56.54 arc-90 38.57,56.51 39.2,57.15 v39.2,60.32 | R8.2 86.83,38.09 84.93,40 IC1.18
N$45
  Bottom 0.406: IC3.10 84.29,33.02 85.56,34.29 85.56,36.83 84.93,37.46 80.48,37.46 IC1.15
N$46
  Bottom 0.305: 88.1,16.51 89.37,17.78 IC3.1
  Bottom 0.406: C11.+ 87.47,15.87 88.1,16.51
N$47
  Bottom 0.406: C11.- 79.21,21.59 84.93,21.59 86.2,22.86 IC3.3
N$48
  Bottom 0.305: U$1.63 25.94,39.43 25.87,39.37 13.17,39.37 12.54,38.73 R4.1
N$49
  Bottom 0.305: U$1.62 26.59,38.73 15.71,38.73 15.08,38.09 R5.1
N$50
  Bottom 0.305: U$1.61 27.24,38.09 18.25,38.09 17.62,37.46 R6.1
N$51
  Bottom 0.305: LED1.K 11.27,29.21 R4.2
N$52
  Bottom 0.305: LED2.K 15.08,28.57 R5.2
N$53
  Bottom 0.305: LED3.K R6.2
N$54
  Bottom 0.305: C12.+ 81.12,26.67 86.83,26.67 88.1,25.4 IC3.4
N$55
  Bottom 0.305: 87.47,29.21 88.73,27.94 IC3.5
  Bottom 0.406: C12.- 79.21,29.21 87.47,29.21
N$56
  Bottom 0.406: C14.+ 75.4,19.05 86.2,19.05 87.47,20.32 IC3.2
N$57
  Bottom 0.406: C13.- 74.77,24.76 76.03,26.03 76.03,29.84 77.94,31.75 84.93,31.75 86.2,30.48 IC3.6
N$58
  Bottom 0.406: IC3.9 79.84,35.55 IC1.14
N$59  (via drill 0.6 pad 1.42)
  Top 0.305: IC3.7 94.45,33.02 95.72,31.75 95.72,16.51 94.45,15.23 81.12,15.23 76.03,10.16 70.96,10.16 69.05,8.25 52.54,8.25 51.27,9.52 51.27,16.51 50,17.78 v44.92,17.78
  Bottom 0.305: X1.2 44.29,12.7 44.29,17.14 v44.92,17.78
N$60  (via drill 0.6 pad 1.42)
  Top 0.305: IC3.8 95.09,35.55 96.99,33.65 96.99,15.87 95.09,13.97 84.93,13.97 83.66,12.7 83.66,10.79 81.75,8.89 71.59,8.89 69.69,6.98 51.91,6.98 50,8.89 50,15.23 49.37,15.87 v41.75,15.87
  Bottom 0.305: v41.75,15.87 X1.3
N$61
  Bottom 0.61: X2.1 95.72,12.02 D1.A
N$62
  Bottom 0.61: IC4.1 62.07,9.52 63.34,8.25 69.69,8.25 70.32,7.62 70.32,5.71 70.96,5.08 79.21,5.08 C15.+ 81.12,7.62 D1.C
N$63
  Bottom 0.406: R9.2 LED4.K
N$64
  Bottom 1.676: K1.P X3.2
N$65
  Bottom 1.676: X3.1 54.45,109.85 54.45,98.29 K1.S
N$66
  Bottom 1.676: X3.3 44.29,109.85 44.29,98.29 K1.O
N$67
  Bottom 0.305: R10.1 LED5.A
N$68
  Bottom 0.305: Q3.2 44.29,73.66 44.92,74.29 R11.1
N$69
  Bottom 0.305: K1.2 43.02,85.09 43.65,85.72 46.19,83.81 D2.A 44.92,76.2 LED5.K Q3.3
N$70
  Bottom 0.305: R11.2 53.18,72.39 52.54,71.75 46.19,71.75 44.29,69.84 V1.19
N$71
  Bottom 0.305: K3.2 24.6,85.09 26.51,82.55 D4.A 26.51,76.83 25.87,76.2 LED7.K Q5.3
N$72
  Bottom 0.305: 63.97,99.69 LED6.K 67.15,100.33 67.78,100.96 71.59,100.96 74.13,98.42 83.66,98.42 87.47,94.61 95.09,94.61 95.72,95.25 95.72,102.23 94.45,103.5 85.94,103.5 K2.2 | 63.97,99.69 Q4.3 | 63.97,99.69 D3.A
N$73
  Bottom 0.305: R13.1 62.7,93.97 65.24,93.97 69.69,98.42 LED6.A
N$74
  Bottom 0.305: R15.1 LED7.A
N$75
  Bottom 0.305: R12.1 59.53,94.61 60.8,95.88 Q4.2
N$76
  Bottom 0.305: R12.2 59.53,75.56 57.62,73.66 56.35,73.66 53.18,70.48 47.46,70.48 46.83,69.84 V1.18
N$77
  Bottom 1.676: K2.P 75.4,106.04 69.05,106.04 67.15,107.94 X4.2
N$78
  Bottom 1.676: K2.S 89.37,100.33 75.4,100.33 72.86,102.87 64.61,102.87 62.07,105.41 62.07,109.85 X4.1
N$79
  Bottom 1.676: K2.O 89.88,111.75 77.31,111.75 75.4,109.85 72.22,109.85 X4.3
N$80
  Bottom 0.406: C17.1 IC2.15
N$81
  Bottom 0.406: C18.1 IC2.10
N$82
  Bottom 0.305: LED8.A 2.38,76.83 2.38,69.84 R17.1
N$83
  Bottom 0.305: Q5.2 25.23,73.66 25.87,74.29 R14.1
N$84
  Bottom 0.305: IC1.27 74.77,57.15 75.4,57.78 JP1.4 75.4,62.86 76.03,63.5 84.93,63.5 86.83,65.4 | 86.83,65.4 OK2.5 | R19.1 86.83,65.4
N$85
  Bottom 0.305: R14.2 34.76,73.66 34.76,69.21 35.4,68.58 36.67,68.58 39.84,65.4 48.73,65.4 49.37,66.03 V1.17
N$86
  Bottom 1.676: K3.P 30.31,109.85 | X5.2 30.31,110.48 | 30.31,109.85 X5.2 | X5.2 30.31,109.85
N$87
  Bottom 1.676: X5.1 35.4,109.85 35.4,98.29 K3.S
N$88
  Bottom 1.676: X5.3 25.23,109.85 25.23,98.29 K3.O
N$89
  Bottom 0.305: OK1.1 97.62,78.1 96.99,78.73 LED9.K
N$90
  Bottom 0.305: K4.2 4.92,85.09 7.45,81.91 D5.A 7.45,77.47 6.19,76.2 LED8.K Q6.3
N$91
  Bottom 0.305: IC1.29 69.69,57.15 70.32,57.78 JP1.2 70.32,65.4 | OK4.5 70.32,65.4 | 70.32,65.4 R21.1
N$92
  Bottom 0.305: Q6.2 6.19,73.66 6.82,74.29 R16.1
N$93
  Bottom 0.305: R16.2 15.08,69.84 15.71,69.21 32.86,69.21 34.76,67.31 36.03,67.31 39.2,64.13 50.64,64.13 51.91,65.4 V1.16
N$94
  Bottom 1.676: X6.1 16.34,109.85 16.34,98.29 K4.S
N$95
  Bottom 1.676: K4.P X6.2
N$96
  Bottom 1.676: X6.3 6.19,109.85 6.19,98.29 K4.O
N$97
  Bottom 0.305: D6.A 96.36,88.26 95.09,86.99 JP4.1 91.28,81.28 95.09,77.47 OK1.2
N$98
  Bottom 0.305: JP5.2 84.93,89.53 85.56,90.17 R22.2
N$99
  Bottom 0.305: LED10.A D7.C R22.1
N$100
  Bottom 0.305: D7.A 88.1,88.26 86.83,86.99 JP5.1 83.02,81.28 86.83,77.47 OK2.2
N$101
  Bottom 0.305: OK2.1 89.37,77.47 LED10.K
N$102
  Bottom 0.305: JP6.2 76.03,89.53 76.67,90.17 R24.2
N$103
  Bottom 0.305: LED11.A D8.C R24.1
N$104
  Bottom 0.305: OK3.1 81.12,77.47 LED11.K
N$105
  Bottom 0.305: D8.A 79.84,88.26 78.58,86.99 JP6.1 74.13,81.91 78.58,77.47 OK3.2
N$106
  Bottom 0.305: JP7.2 68.42,89.53 69.05,90.17 R25.2
N$107
  Bottom 0.305: D9.A 71.59,87.62 70.96,86.99 JP7.1 66.51,81.28 70.32,77.47 OK4.2
N$108
  Bottom 0.305: OK4.1 72.86,77.47 LED12.K
N$109
  Bottom 0.305: LED12.A D9.C R25.1
VCC  (via drill 0.6 pad 1.42)
  Top 0.305: IC1.10 64.61,39.37 63.34,38.09 v40.48,38.09 37.94,35.55 37.94,31.11 36.67,29.84 21.43,29.84 19.52,27.94 8.09,27.94 C4.1 | IC3.16 86.83,17.78 88.1,19.05 88.1,23.49 88.73,24.12 92.55,24.12 93.81,25.4 R8.1 | R20.2 77.31,63.5 77.31,62.86 | 63.97,62.86 76.67,62.86 77.31,62.86 | 63.97,62.86 63.34,62.23 63.34,57.78 62.07,56.51 IC1.32 | D2.C 60.8,73.02 60.8,66.03 63.97,62.86 | R18.2 77.94,62.86 77.31,62.86
  Bottom 0.305: 36.67,57.84 37.3,57.84 | 36.67,57.84 37.24,57.84 arc-90 37.3,57.78 37.3,57.19 U$1.32 | 36.67,57.84 U$1.31 | U$1.15 23.99,61.59 24.6,61.59 | 24.6,61.59 24.6,59.69 24.64,59.69 U$1.16 24.64,61.59 24.6,61.59 | 24.6,61.59 25.23,61.59 25.23,59.69 | 25.23,59.69 25.29,59.69 U$1.17 25.23,59.86 25.23,59.69 | 18.14,57.78 U$1.6 | 25.23,59.69 25.23,57.78 18.25,57.78 | 18.25,57.78 18.14,57.78 | 18.14,57.78 18.14,63.61 15.71,66.03 15.71,67.94 | U$1.57 29.84,45.56 29.68,45.72 24.6,45.72 | 21.43,45.72 24.6,45.72 | U$1.70 21.39,45.68 21.43,45.72 | U$1.65 24.64,45.68 24.6,45.72 | 16.87,50.69 U$1.89 8.2,50.69 arc-90 8.09,50.8 C1.1 | 16.87,50.69 18.25,52.06 18.25,57.78 | 16.87,50.69 21.43,46.14 21.43,45.72 | LED1.A LED2.A | LED1.A LED3.A | JP1.1 67.78,57.78 67.15,57.15 IC1.30 67.15,52.06 68.42,50.8 68.42,38.73 67.78,38.09 64.61,38.09 | U$1.47 40.48,47.44 v40.48,38.09 | LED4.A 69.69,3.17 69.05,3.81 69.05,6.35 68.42,6.98 61.43,6.98 60.16,8.25 60.16,13.97 61.43,15.23 | 61.43,15.23 66.51,15.23 67.15,14.6 IC4.3 | IC1.32 62.07,45.08 64.61,42.54 IC1.10 64.61,38.09 | 64.61,38.09 64.61,34.92 R3.2 62.07,29.84 | 61.43,15.23 62.07,15.87 62.07,29.84 | C4.1 6.82,24.76 7.45,24.12 LED1.A | C1.1 6.19,50.16 5.55,49.53 5.55,38.73 3.01,36.19 3.01,30.48 C8.1 | C4.1 C8.1 | C4.1 C8.1 | 62.07,29.84 C10.1 C9.1 | R20.2 R21.2 | R18.2 R19.2 | D5.C 16.98,78.73 16.98,85.09 K4.1 20.28,88.26 25.87,88.26 27.78,86.36 27.78,80.64 29.05,79.37 36.67,79.37 | K3.1 36.67,85.09 36.67,79.37 | 36.67,79.37 D4.C 36.67,73.02 R10.2 | 55.08,85.09 55.72,85.72 55.72,85.59 K1.1 55.08,85.09 | 80.48,97.15 K2.1 80.48,96.52 81.12,97.15 75.4,97.15 D3.C 71.59,93.34 67.15,93.34 60.8,86.99
  Bottom 0.305: 36.67,57.84 36.67,57.78 | 36.67,57.84 36.67,64.77 35.4,66.03 33.49,66.03 R1.2 15.71,67.94 | D5.C 13.81,78.1 13.17,77.47 13.17,69.21 14.44,67.94 15.71,67.94 | R15.2 17.62,73.02 D5.C | 60.8,86.99 R13.2 | 60.8,86.99 56.99,86.99 55.08,85.09 | D2.C 55.08,78.73 55.08,85.09 | R17.2 7.45,57.15 C1.1
  Bottom 0.406: IC3.16 75.4,17.78 C14.-
  Bottom 0.61: IC4.3 C16.+ 73.5,12.7 C14.-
